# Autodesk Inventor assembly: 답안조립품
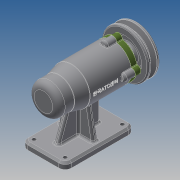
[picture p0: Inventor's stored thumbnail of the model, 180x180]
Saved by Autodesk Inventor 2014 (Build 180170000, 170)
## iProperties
Created: 2019-07
Part Number: 답안조립품
Document SubType Name: Assembly
Designer: kb542-3
Author: kb542-3
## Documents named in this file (12)
- C:\Users\kb542-3\Desktop\490704V1078 (1)\답안조립품.iam
- C:\Users\kb542-3\Desktop\490704V1078 (1)\본체.ipt
- C:\Users\kb542-3\Desktop\490704V1078 (1)\V벨트풀리.ipt
- C:\Users\kb542-3\Desktop\490704V1078 (1)\멈춤나사 M3.ipt
- C:\Users\kb542-3\Desktop\490704V1078 (1)\베어링 6004.ipt
- C:\Users\kb542-3\Desktop\490704V1078 (1)\베어링 51202.ipt
- C:\Users\kb542-3\Desktop\490704V1078 (1)\볼트 M4.ipt
- C:\Users\kb542-3\Desktop\490704V1078 (1)\어댑터슬리브.ipt
- C:\Users\kb542-3\Desktop\490704V1078 (1)\오일 실.ipt
- C:\Users\kb542-3\Desktop\490704V1078 (1)\축.ipt
- C:\Users\kb542-3\Desktop\490704V1078 (1)\커버.ipt
- C:\Users\kb542-3\Desktop\490704V1078 (1)\키 5 x 5 x 16.ipt
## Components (1 placed, 1 different names)
1. V벨트풀리:1 — 플러쉬:1
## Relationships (1: Flush 1)
- 플러쉬:1 [Flush]: V벨트풀리:1
